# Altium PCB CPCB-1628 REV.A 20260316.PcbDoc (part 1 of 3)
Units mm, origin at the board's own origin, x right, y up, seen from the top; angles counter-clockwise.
Board outline 103 x 58.8 mm, 4 copper layers (Top Layer 1, Layer1, Layer2, Bottom Layer 1), stack 0.603 mm thick; 176 components, 137 nets, 518 pads, 340 vias.
Unrouted connection lines stored in the file: 10.
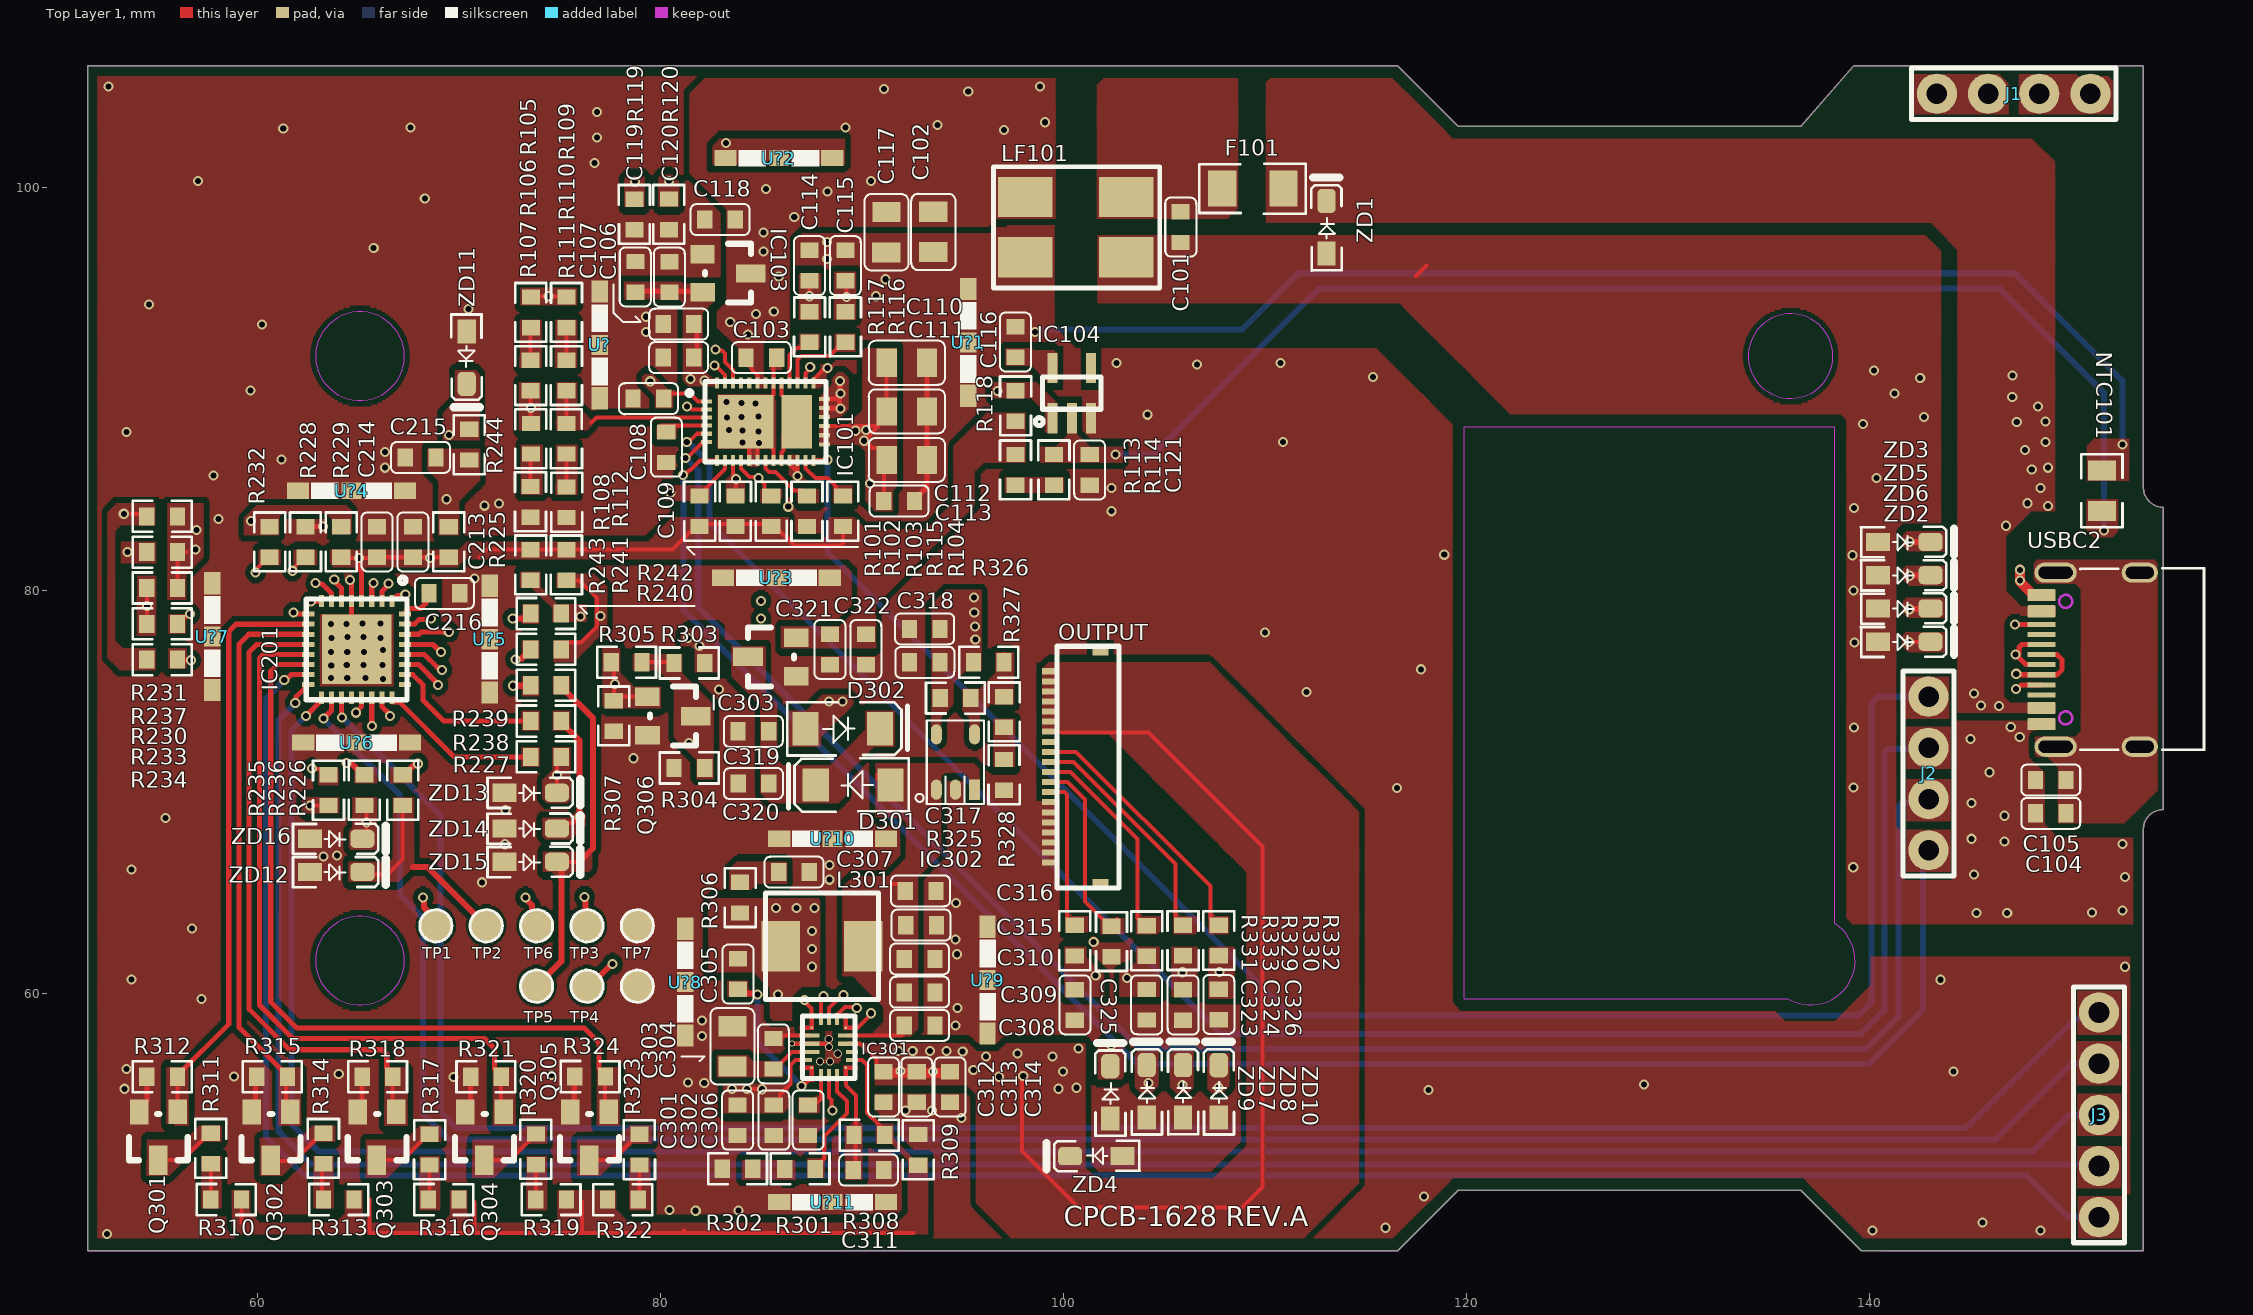
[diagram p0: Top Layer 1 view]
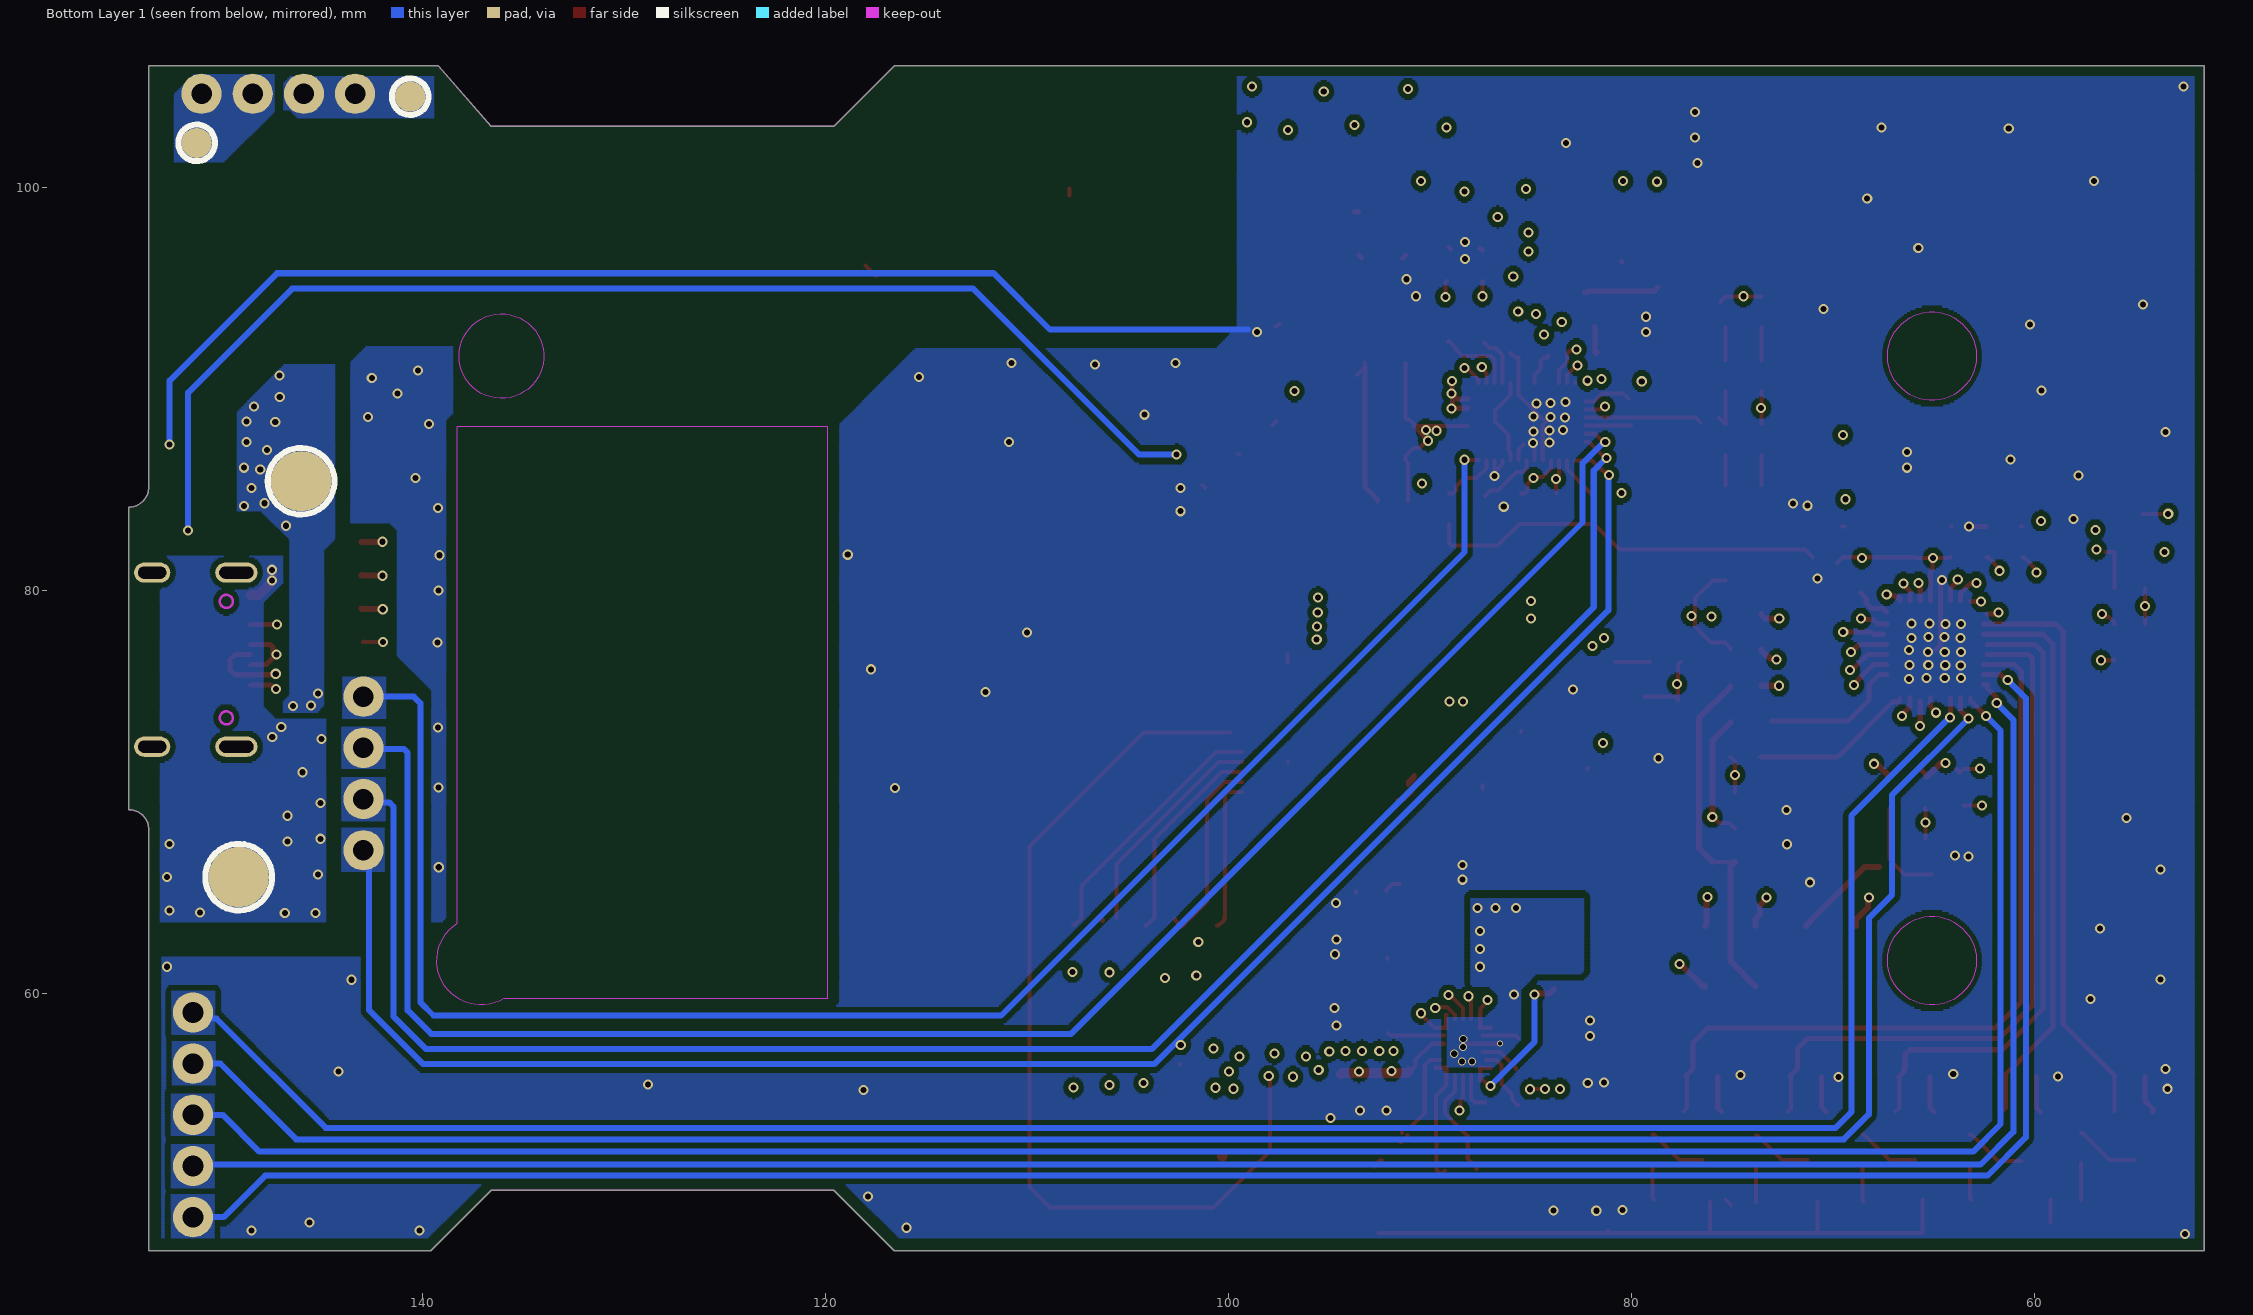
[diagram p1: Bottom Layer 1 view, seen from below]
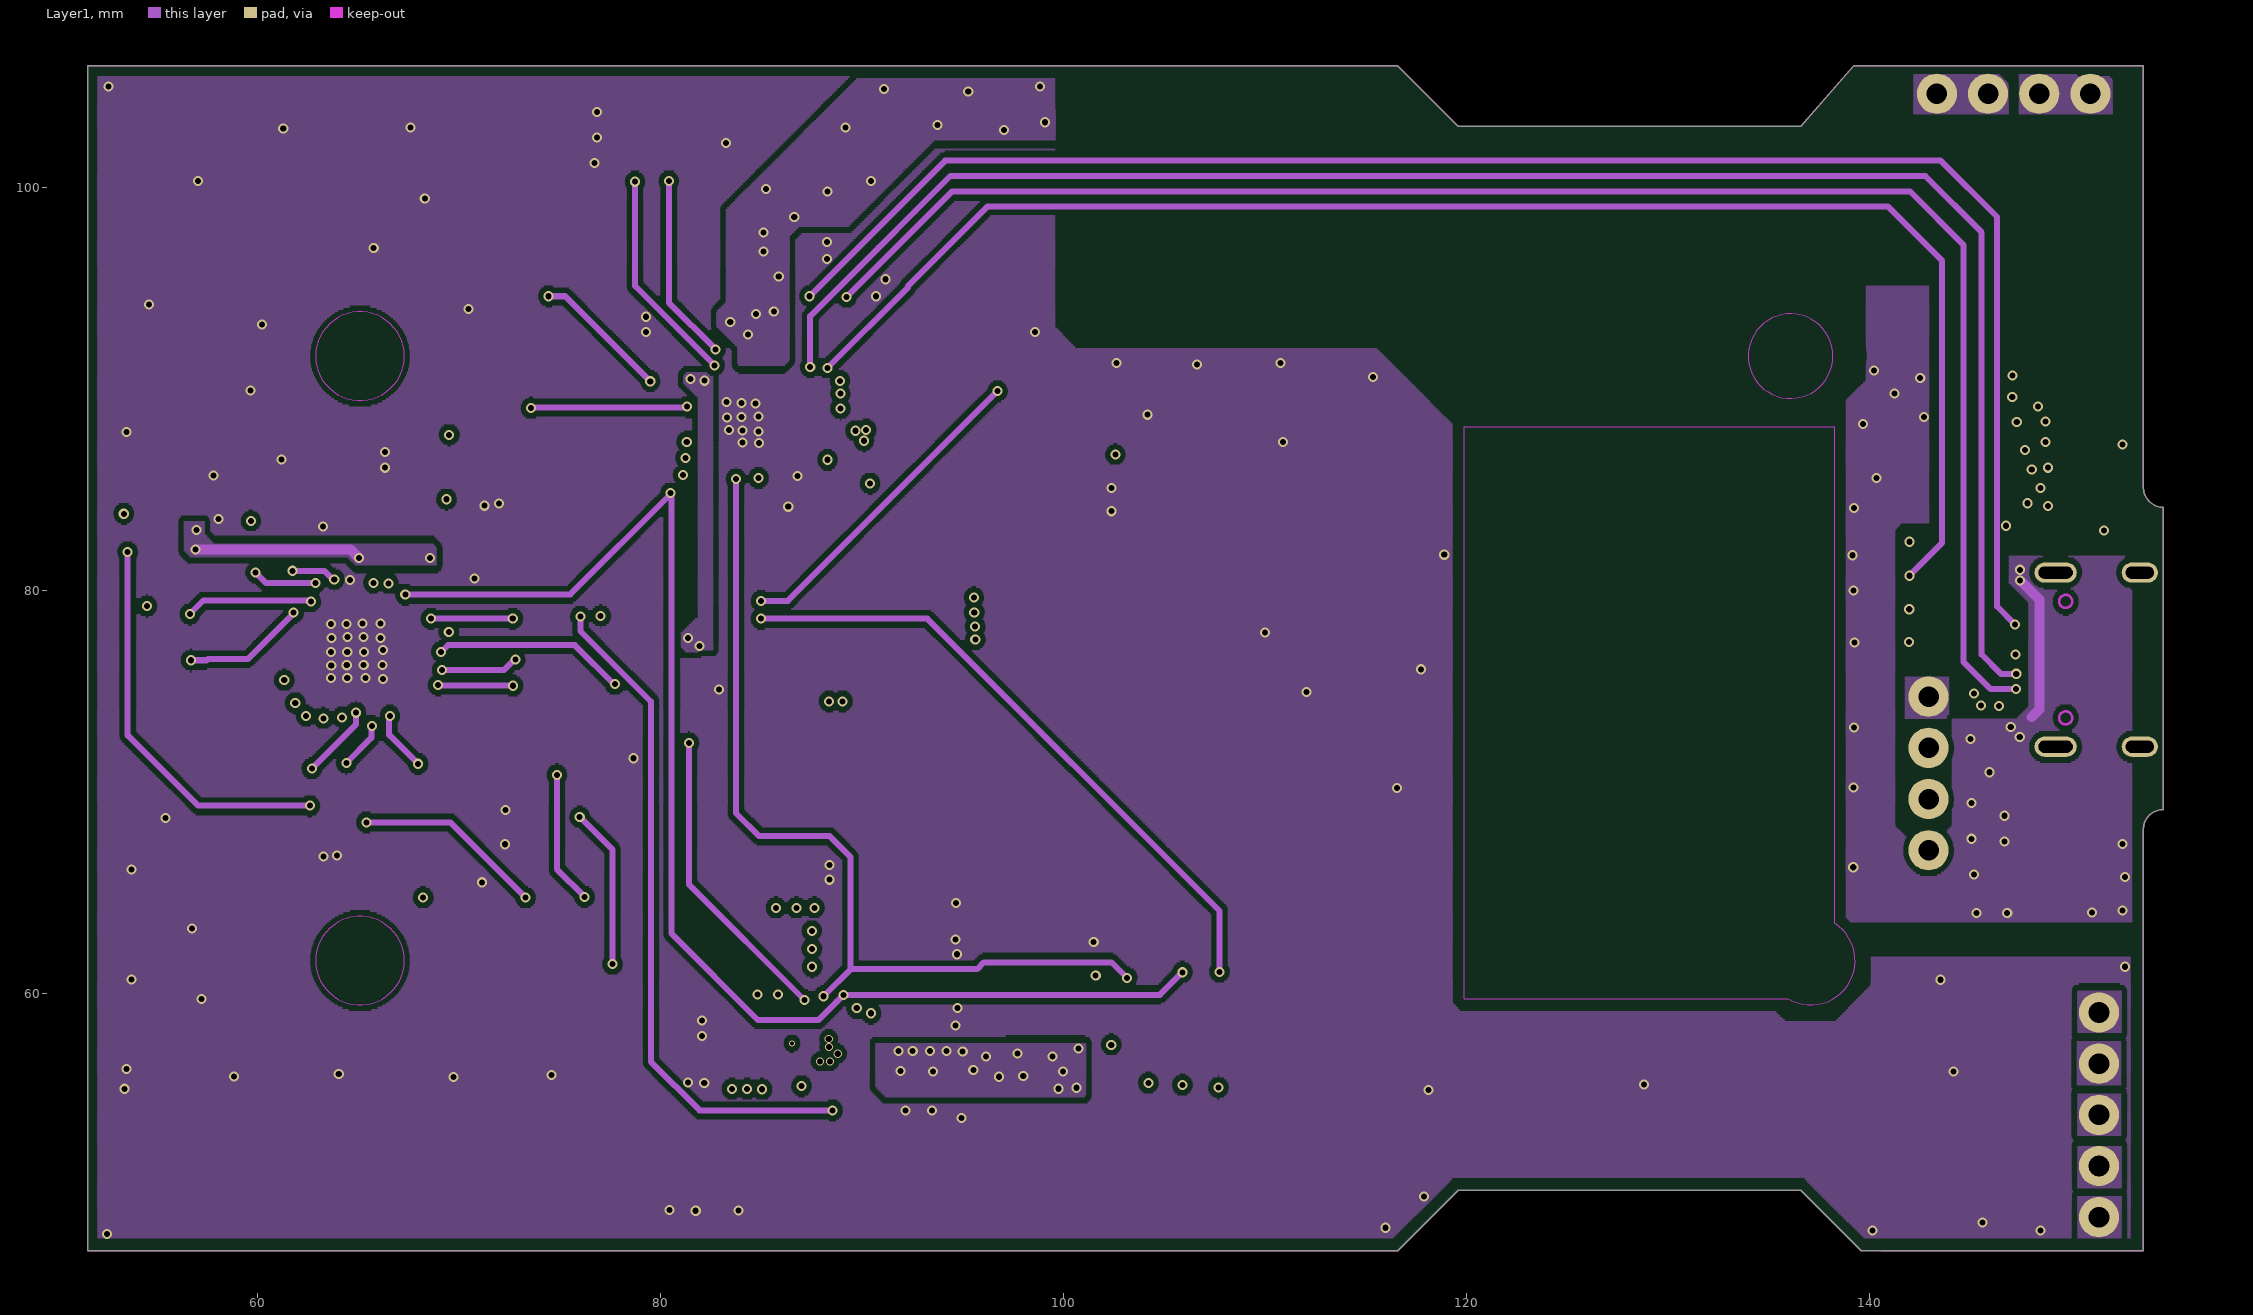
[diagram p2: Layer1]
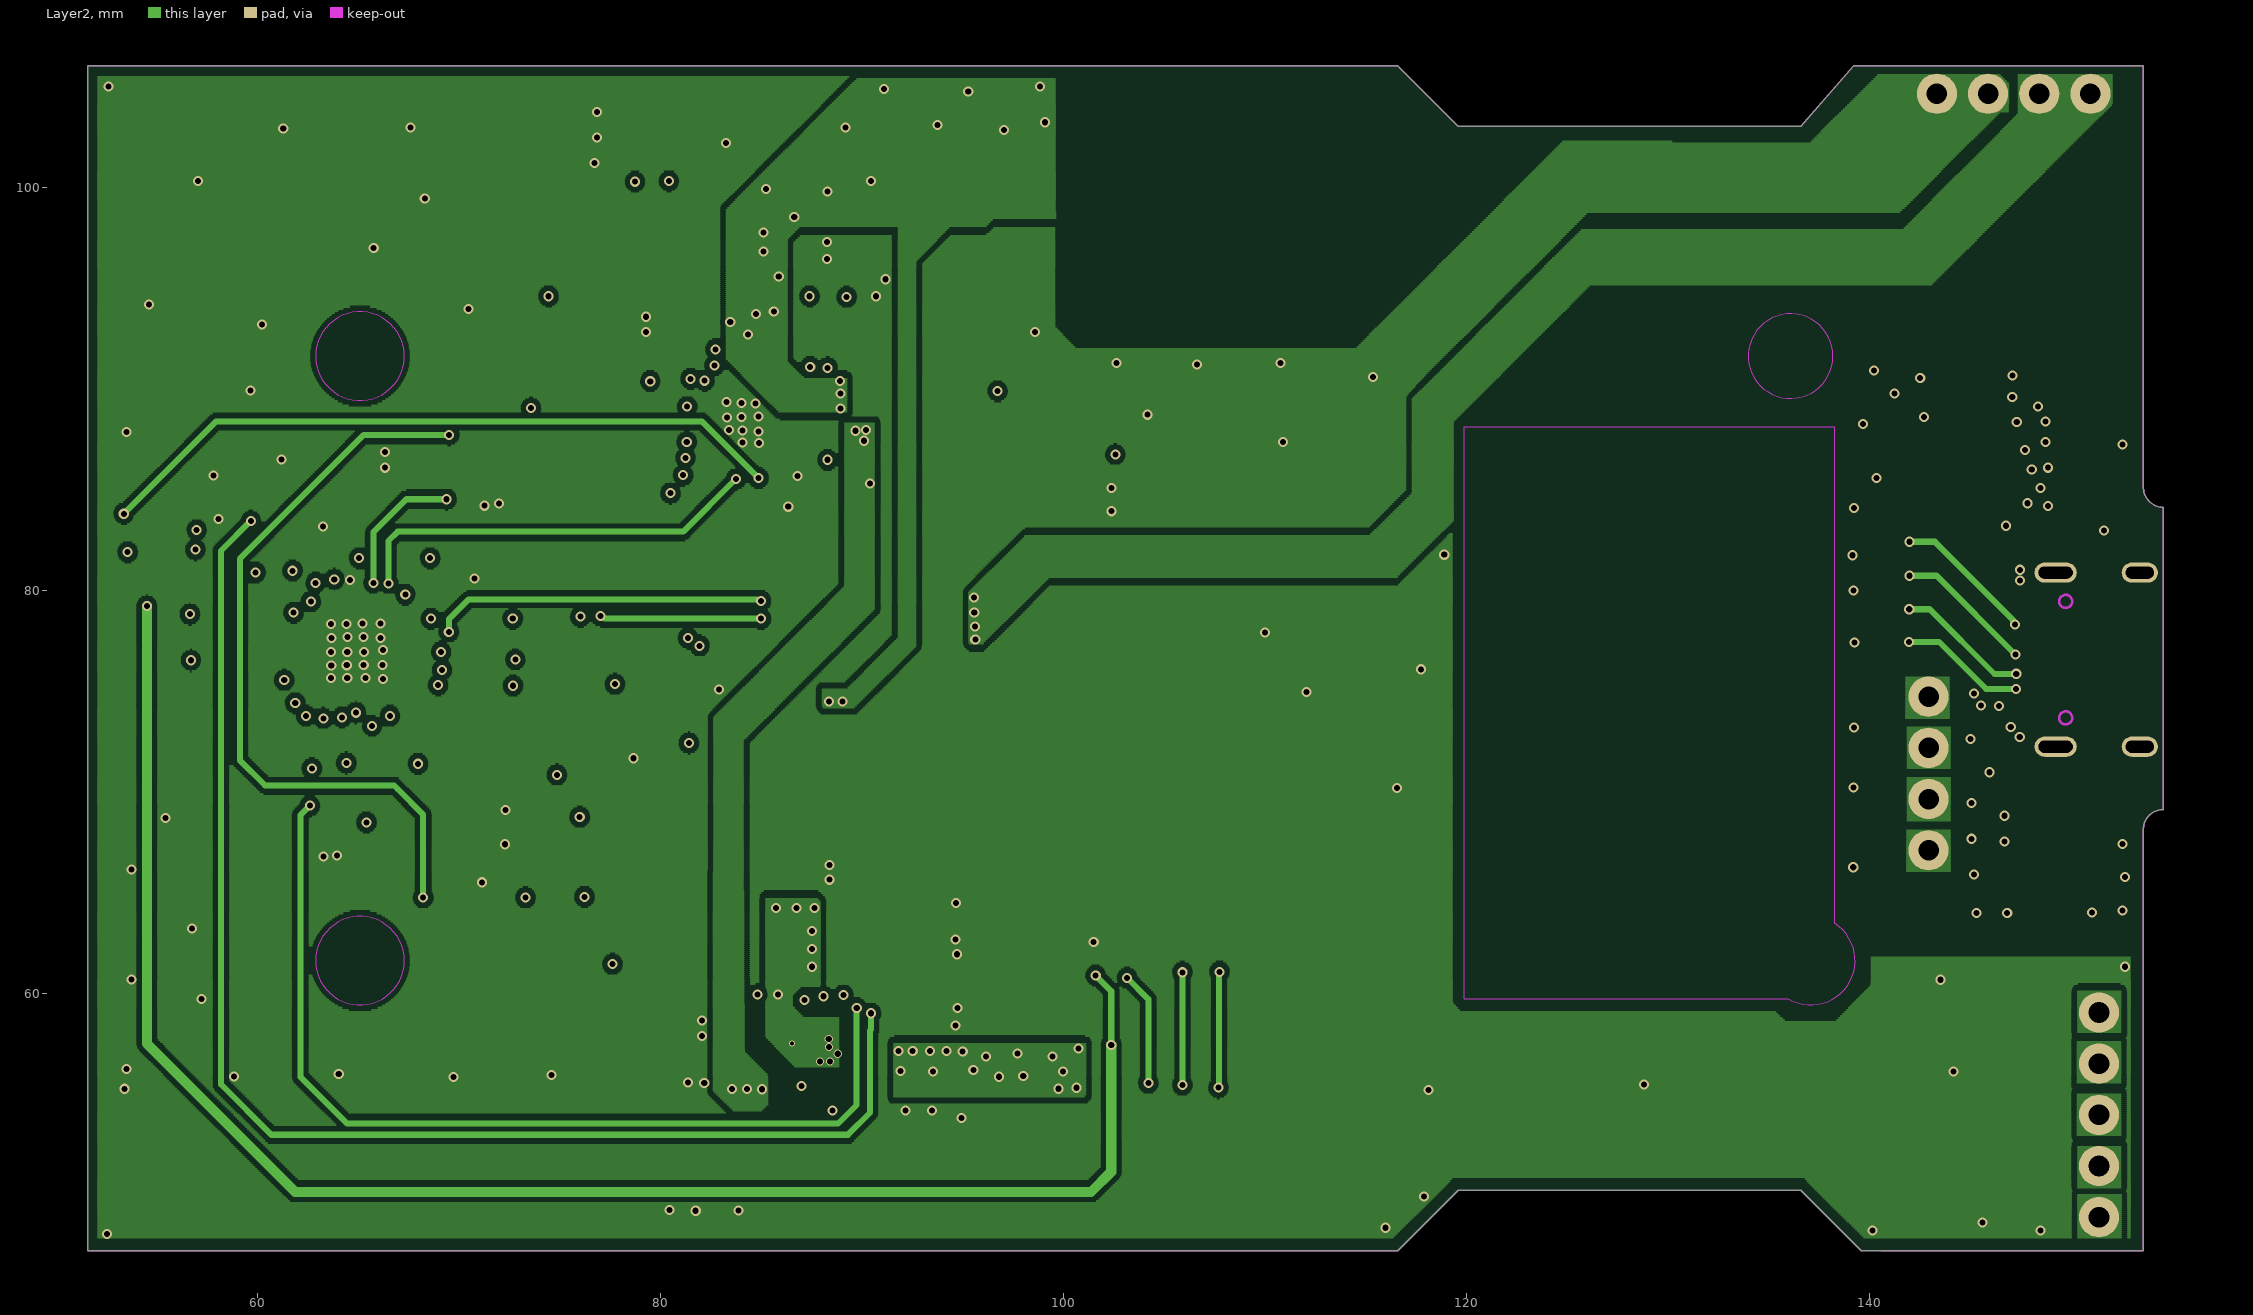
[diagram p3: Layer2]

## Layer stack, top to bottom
Top Solder: solder mask 0.0102, Solder Resist, Dk 3.5
Top Layer 1: signal copper 0.035
Dielectric 1: core 0.0711, PP-006, Dk 4.1
Layer1: signal copper 0.0356
Dielectric 2: dielectric 0.32, FR-4, Dk 4.8
Layer2: signal copper 0.0356
Dielectric 3: core 0.0711, PP-006, Dk 4.1
Bottom Layer 1: signal copper 0.035
Bottom Solder: solder mask 0.0102, Solder Resist, Dk 3.5

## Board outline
51.563,47.243 116.563,47.243 119.563,50.243 136.563,50.243 139.563,47.243 153.563,47.243 153.563,68.143 cw(c154.563,68.143) 154.563,69.143 154.563,84.143 cw(c154.563,85.143) 153.563,85.143 153.563,106.043 139.188,106.043 136.563,103.043 119.563,103.043 116.563,106.043 51.563,106.043

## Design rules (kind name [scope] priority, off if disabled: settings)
Clearance [All] p1: gap=0.254 ignorepadtopadclearanceinfootprint=FALSE except(0: Arc-Hole Track-Hole SMDPad-Hole THPad-Hole Via-Hole Fill-Hole Poly-Hole Region-Hole Text-Hole)
PlaneConnect [All] p1: planeconnectstyle=Direct reliefexpansion=0.508 reliefentries=4 reliefconductorwidth=0.254 reliefairgap=0.254
PolygonConnect [All] p1: connectstyle=Direct reliefconductorwidth=0.254 reliefentries=4 polygonreliefangle="90 Angle" airgapwidth=0.254
RoutingVias [All] p1: holewidth=0.711 width=1.27 viastyle="Through Hole" minholewidth=0.711 minwidth=1.27 maxholewidth=0.711 maxwidth=1.27
SolderMaskExpansion [All] p1: expansion=0.102 istentingtop=FALSE
Width [All] p1: maxlimit=0.5 minlimit=0.2 preferedwidth=0.2
29 further rules are at their usual default settings.

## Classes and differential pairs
component class "CHR-0807.REV.0  20260309": C101 C102 C103 C106 C107 C108 C109 C110 C111 C112 C113 C114 C115 C116 C117 C118 C119 C120 C213 C214 C215 C216 C301 C302 C303 C304 C305 C306 C307 C308 C309 C310 C311 C312 C313 C314 C315 C316 C317 C318 C319 C320 C321 C322 C323 C324 C326 D301 D302 F101 IC101 IC201 IC301 IC302 IC303 LF101 NTC101 P1 P2 Q301 Q302 Q303 Q304 Q305 Q306 R101 R102 R103 R104 R105 R106 R107 R108 R109 R110 R111 R112 R113 R114 R115 R116 R117 R118 R225 R226 R227 R228 R230 R231 R232 R233 R234 R235 R236 R237 R238 R239 R240 R241 R242 R243 R244 R301 R302 R303 R304 R305 R306 R307 R308 R309 R310 R311 R312 R313 R314 R315 R316 R317 R318 R320 R321 R322 R323 R324 R325 R326 R327 R328 R329 R330 R331 R332 R333 ZD1 ZD2 ZD3 ZD4 ZD5 ZD6 ZD7 ZD8 ZD9 ZD10 ZD11 ZD12 ZD13 ZD14 ZD15 ZD16

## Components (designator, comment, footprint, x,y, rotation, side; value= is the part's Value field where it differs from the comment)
C101 "0.1uF/50V" 0603-T-C 105.791,98.044 r270 top
C102 "10uF/25V" 0805-T-C 93.515,97.808 r270 top
C103 "0.1uF/50V" 0603-T-C 84.983,91.567 r0 top
C104 "0.1uF/50V" 0603-T-C 148.971,68.961 r180 top
C105 "0.1uF/50V" 0603-T-C 148.971,70.612 r180 top
C106 "10uF/10V" 0603-T-C 80.874,91.576 r180 top
C107 "0.1uF/50V" 0603-T-C 80.874,93.233 r180 top
C108 "10uF/10V" 0603-T-C 79.375,89.535 r180 top
C109 "10uF/10V" 0603-T-C 80.264,87.122 r270 top
C110 "22uF/25V" 0805-T-C 92.202,91.313 r0 top
C111 "22uF/25V" 0805-T-C 92.202,88.9 r0 top
C112 "22uF/25V" 0805-T-C 92.202,86.487 r0 top
C113 "0.1uF/50V" 0603-T-C 91.823,84.455 r0 top
C114 "330pF/50V" 0603-T-C 87.376,96.139 r90 top
C115 "330pF/50V" 0603-T-C 89.154,96.139 r90 top
C116 "1UF/50V" 0603-T-C 97.596,92.348 r90 top
C117 "10uF/25V" 0805-T-C 91.186,97.79 r270 top
C118 "0.1uF/50V" 0603-T-C 82.931,98.425 r180 top
C119 "10uF/10V" 0603-T-C 78.729,95.58 r90 top
C120 "0.1uF/50V" 0603-T-C 80.419,95.567 r90 top
C121 "1UF/50V" 0603-T-C 101.279,85.998 r90 top (schematic designator C116)
C213 "10uF/10V" 0603-T-C 67.691,82.423 r90 top
C214 "0.1uF/50V" 0603-T-C 65.913,82.423 r90 top
C215 "10nF/50V" 0603-T-C 68.072,86.614 r0 top
C216 "0.47uF/16V" 0603-T-C 69.249,79.877 r180 top
C301 "1uF/25V" 0603-T-C 83.802,53.721 r270 top
C302 "0.1uF/50V" 0603-T-C 85.597,53.723 r270 top
C303 "10uF/25V" 0805-T-C 83.549,57.388 r90 top
C304 "0.1uF/50V" 0603-T-C 85.58,57.023 r90 top
C305 "47nF/50V" 0603-T-C 83.827,60.978 r90 top
C306 "4.7uF/10V" 0603-T-C 87.299,53.721 r270 top
C307 "NC" 0603-T-C 86.598,66.04 r180 top
C308 "22uF/10V" 0603-T-C 92.837,58.42 r0 top
C309 "22uF/10V" 0603-T-C 92.837,60.071 r0 top
C310 "0.1uF/50V" 0603-T-C 92.837,61.722 r0 top
C311 "0.1uF/50V" 0603-T-C 90.303,51.247 r0 top
C312 "10uF/10V" 0603-T-C 91.041,55.372 r270 top
C313 "10uF/10V" 0603-T-C 92.692,55.372 r270 top
C314 "0.1uF/50V" 0603-T-C 94.343,55.372 r270 top
C315 "4.7uF/10V" 0603-T-C 92.912,63.401 r0 top
C316 "0.1uF/50V" 0603-T-C 92.886,65.102 r0 top
C317 "0.1uF/50V" 0603-T-C 93.091,76.454 r180 top
C318 "4.7uF/10V" 0603-T-C 93.091,78.105 r0 top
C319 "10uF/10V" 0603-T-C 84.582,73.025 r180 top
C320 "0.1uF/50V" 0603-T-C 84.59,70.428 r0 top
C321 "0.1uF/50V" 0603-T-C 88.392,77.089 r90 top
C322 "4.7uF/10V" 0603-T-C 90.17,77.089 r90 top
C323 "0.1uF/50V" 0603-T-C 104.106,59.454 r90 top
C324 "0.1uF/50V" 0603-T-C 105.91,59.44 r270 top
C325 "0.1uF/50V" 0603-T-C 100.537,59.444 r270 top
C326 "0.1uF/50V" 0603-T-C 107.681,59.467 r270 top
D301 "SS145" SMAF 89.535,70.358 r0 top
D302 "NU" SMAF 89.027,73.152 r180 top
F101 "F1206HI5000V032TM" 1206-T-R 109.377,99.957 r180 top
IC101 "TPS25751D" QFN-38PIN 85.181,88.392 r0 top
IC103 "CE6022818M" SOT-23 83.312,95.758 r270 top (schematic designator IC303)
IC104 "PST8411" SSOP5 100.39,89.808 r0 top (schematic designator IC102)
IC201 "MSPM0L1105TRHB" QFN-32PIN 64.897,77.089 r270 top
IC301 "BQ25622" QFN-(3_2.5)-18PIN 88.29,57.403 r90 top
IC302 "CE6300" SOT-23(5PIN) 94.615,71.501 r90 top
IC303 "CE6022818M" SOT-23 85.471,76.708 r90 top
J1 "0603" CK_DIP-(10.16_2.54)-4PIN 147.132,104.665 r0 top (schematic designator R302)
J2 "0603" CK_DIP-(10.16_2.54)-4PIN 142.909,70.932 r270 top (schematic designator R302)
J3 "0603" CK_DIP-(10.16_2.54)-6PIN 151.367,59.07 r270 top (schematic designator R302)
L301 "1uH 7A SMP0530" LF-SMD-(5.6_5.3) 87.993,62.357 r0 top
LF101 "LF-ACT45B" CMF7060 100.584,98.044 r270 top
NTC101 "471K" 0805-T-R 151.511,84.963 r270 top
OUTPUT "1k/0603" DZ-(12_3)-20PIN 100.552,71.247 r90 top (schematic designator R304)
Q301 "CJ3400" SOT-23 55.056,52.897 r180 top
Q302 "CJ3400" SOT-23 60.643,52.897 r180 top
Q303 "CJ3400" SOT-23 65.914,52.897 r180 top
Q304 "CJ3400" SOT-23 71.247,52.897 r180 top
Q305 "CJ3400" SOT-23 76.454,52.897 r180 top
Q306 "CJ3400" SOT-23 80.58,73.788 r270 top
R101 "3.3K/0603" 0603-T-R 81.915,83.947 r270 top
R102 "3.3K/0603" 0603-T-R 83.693,83.947 r270 top
R103 "10K/0603" 0603-T-R 85.471,83.947 r270 top
R104 "10K/0603" 0603-T-R 89.027,83.947 r270 top
R105 "2K/0603" 0603-T-R 73.543,93.816 r90 top
R106 "100K/0603" 0603-T-R 73.533,90.68 r90 top
R107 "2K/0603" 0603-T-R 73.543,87.542 r90 top
R108 "2K/0603" 0603-T-R 73.525,84.414 r90 top
R109 "2K/0603" 0603-T-R 75.312,93.816 r90 top
R110 "100K/0603" 0603-T-R 75.311,90.68 r90 top
R111 "2K/0603" 0603-T-R 75.308,87.542 r90 top
R112 "2K/0603" 0603-T-R 75.318,84.391 r90 top
R113 "10K/0603" 0603-T-R 97.596,85.998 r90 top (schematic designator R118)
R114 "10K/0603" 0603-T-R 99.501,85.998 r270 top (schematic designator R118)
R115 "0R/0603" 0603-T-R 87.249,83.947 r90 top
R116 "10R/0603" 0603-T-R 89.154,93.091 r270 top
R117 "10R/0603" 0603-T-R 87.376,93.091 r90 top
R118 "10K/0603" 0603-T-R 97.596,89.173 r270 top
R119 "10R/0603" 0603-T-R 78.682,98.677 r270 top (schematic designator R117)
R120 "10R/0603" 0603-T-R 80.391,98.679 r270 top (schematic designator R117)
R225 "47K/0603" 0603-T-R 69.469,82.423 r270 top
R226 "100R/0603" 0603-T-R 67.183,70.104 r90 top
R227 "100R/0603" 0603-T-R 74.295,71.755 r0 top
R228 "100K/0603" 0603-T-R 62.357,82.423 r90 top
R229 "10K/0603" 0603-T-R 64.135,82.423 r270 top
R230 "10K/0603" 0603-T-R 55.245,80.137 r180 top
R231 "10K/0603" 0603-T-R 55.245,83.693 r0 top
R232 "100R/0603" 0603-T-R 60.579,82.423 r90 top
R233 "100R/0603" 0603-T-R 55.245,78.359 r180 top
R234 "100R/0603" 0603-T-R 55.245,76.581 r180 top
R235 "100R/0603" 0603-T-R 63.5,70.104 r270 top
R236 "100R/0603" 0603-T-R 65.278,70.104 r90 top
R237 "10K/0603" 0603-T-R 55.245,81.915 r0 top
R238 "100R/0603" 0603-T-R 74.295,73.533 r0 top
R239 "100R/0603" 0603-T-R 74.295,75.311 r0 top
R240 "100R/0603" 0603-T-R 74.295,77.089 r0 top
R241 "10K/0603" 0603-T-R 75.311,81.282 r90 top
R242 "100R/0603" 0603-T-R 74.295,78.867 r0 top
R243 "10K/0603" 0603-T-R 73.533,81.282 r90 top
R244 "100R/0603" 0603-T-R 70.485,87.249 r90 top
R301 "0603" 0603-T-R 86.904,51.308 r0 top
R302 "0603" 0603-T-R 83.799,51.313 r0 top
R303 "10K/0603" 0603-T-R 81.405,76.413 r0 top
R304 "1k/0603" 0603-T-R 81.405,71.206 r180 top
R305 "100R/0603" 0603-T-R 78.296,76.455 r180 top
R306 "NC" 0603-T-R 83.929,64.77 r270 top
R307 "100k/0603" 0603-T-R 77.659,73.788 r270 top
R308 "0603" 0603-T-R 90.34,52.986 r180 top
R309 "0603" 0603-T-R 92.77,52.255 r270 top
R310 "0603" 0603-T-R 58.42,49.784 r0 top
R311 "0603" 0603-T-R 57.658,52.324 r270 top
R312 "10K/0603" 0603-T-R 55.247,55.88 r0 top
R313 "0603" 0603-T-R 64.008,49.784 r0 top
R314 "0603" 0603-T-R 63.246,52.324 r270 top
R315 "10K/0603" 0603-T-R 60.706,55.88 r0 top
R316 "0603" 0603-T-R 69.215,49.784 r0 top
R317 "0603" 0603-T-R 68.518,52.262 r90 top
R318 "10K/0603" 0603-T-R 65.933,55.883 r0 top
R319 "0603" 0603-T-R 74.549,49.784 r0 top
R320 "0603" 0603-T-R 73.79,52.281 r90 top
R321 "10K/0603" 0603-T-R 71.312,55.88 r0 top
R322 "0603" 0603-T-R 78.105,49.784 r180 top
R323 "0603" 0603-T-R 78.932,52.262 r90 top
R324 "10K/0603" 0603-T-R 76.483,55.887 r0 top
R325 "12K/0603" 0603-T-R 94.615,74.676 r180 top
R326 "12K/0603" 0603-T-R 96.266,76.454 r180 top
R327 "1K/0603" 0603-T-R 97.03,73.985 r90 top
R328 "1K/0603" 0603-T-R 97.028,70.866 r90 top
R329 "100R/0603" 0603-T-R 104.106,62.622 r90 top
R330 "100R/0603" 0603-T-R 105.91,62.64 r90 top
R331 "100R/0603" 0603-T-R 100.537,62.632 r90 top
R332 "100R/0603" 0603-T-R 107.681,62.642 r90 top
R333 "100R/0603" 0603-T-R 102.359,62.59 r90 top
U? "Comment" SMD_3P-L6.7-W0.9-R3-P2.65-ICSRC6508SFR 76.962,92.202 r90 top
U?1 "Comment" SMD_3P-L6.7-W0.9-R3-P2.65-ICSRC6508SFR 95.25,92.329 r90 top
U?2 "Comment" SMD_3P-L6.7-W0.9-R3-P2.65-ICSRC6508SFR 85.852,101.473 r180 top
U?3 "Comment" SMD_3P-L6.7-W0.9-R3-P2.65-ICSRC6508SFR 85.725,80.645 r180 top
U?4 "Comment" SMD_3P-L6.7-W0.9-R3-P2.65-ICSRC6508SFR 64.643,84.963 r180 top
U?5 "Comment" SMD_3P-L6.7-W0.9-R3-P2.65-ICSRC6508SFR 71.501,77.597 r270 top
U?6 "Comment" SMD_3P-L6.7-W0.9-R3-P2.65-ICSRC6508SFR 64.897,72.463 r0 top
U?7 "Comment" SMD_3P-L6.7-W0.9-R3-P2.65-ICSRC6508SFR 57.731,77.724 r90 top
U?8 "Comment" SMD_3P-L6.7-W0.9-R3-P2.65-ICSRC6508SFR 81.207,60.579 r90 top
U?9 "Comment" SMD_3P-L6.7-W0.9-R3-P2.65-ICSRC6508SFR 96.209,60.674 r90 top
U?10 "Comment" SMD_3P-L6.7-W0.9-R3-P2.65-ICSRC6508SFR 88.519,67.691 r180 top
U?11 "Comment" SMD_3P-L6.7-W0.9-R3-P2.65-ICSRC6508SFR 88.519,49.657 r0 top
USBC2 "TYPE-C16PIN" TYPE-C-16pin 151.003,76.581 r0 top (schematic designator USBC1)
ZD1 "ESD24C" SOD-323-B 113.03,98.044 r270 top
ZD2 "ESD24C" SOD-323-B 141.705,77.47 r180 top
ZD3 "ESD24C" SOD-323-B 141.705,82.423 r180 top
ZD4 "ESD05C" SOD-323-B 101.6,51.943 r0 top
ZD5 "ESD05C" SOD-323-B 141.705,80.772 r180 top
ZD6 "ESD05C" SOD-323-B 141.705,79.121 r180 top
ZD7 "ESD05C" SOD-323-B 104.106,55.156 r270 top
ZD8 "ESD05C" SOD-323-B 105.91,55.163 r270 top
ZD9 "ESD05C" SOD-323-B 102.297,55.103 r270 top
ZD10 "ESD05C" SOD-323-B 107.681,55.156 r270 top
ZD11 "ESD05C" SOD-323-B 70.358,91.567 r90 top
ZD12 "ESD05C" SOD-323-B 63.881,66.04 r180 top
ZD13 "ESD05C" SOD-323-B 73.533,69.977 r180 top
ZD14 "ESD05C" SOD-323-B 73.533,68.199 r180 top
ZD15 "ESD05C" SOD-323-B 73.533,66.548 r180 top
ZD16 "ESD05C" SOD-323-B 63.881,67.691 r180 top

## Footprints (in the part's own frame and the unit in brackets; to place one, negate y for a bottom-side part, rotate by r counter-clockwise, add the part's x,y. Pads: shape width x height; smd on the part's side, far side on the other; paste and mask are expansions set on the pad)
0603-T-C [mm]
  rect 0.76x0.9 smd mask+0.05: 1(-0.76,0) 2(0.76,0)
  silkscreen extent -1.47,-0.76 1.46,0.78
0603-T-R [mm]
  rect 0.76x0.9 smd mask+0.05: 1(-0.76,0) 2(0.76,0)
  silkscreen extent -1.46,-0.77 1.46,0.77
0805-T-C [mm]
  rect 1x1.4 smd mask+0.05: 1(-1,0.001) 2(1,-0.001)
  silkscreen extent -1.9,-1.1 1.9,1.1
0805-T-R [mm]
  rect 1x1.4 smd mask+0.05: 1(-1,0.001) 2(1,-0.001)
  silkscreen extent -1.82,-1.02 1.82,1.02
1206-T-R [mm]
  rect 1.4x1.78 smd: 1(-1.52,0) 2(1.52,0)
  silkscreen extent -2.63,-1.24 2.66,1.24
CK_DIP-(10.16_2.54)-4PIN [mm]
  round 2 hole 1.02 mask+0.05: 1(-3.81,0) 2(-1.27,0)
  round 2 hole 1.02: 3(1.27,0) 4(3.81,0)
  silkscreen extent -5.08,-1.27 5.08,1.27
CK_DIP-(10.16_2.54)-6PIN [mm]
  round 2 hole 1.02: 1(0,0) 2(2.54,0) 3(5.08,0) 4(7.62,0) 5(10.16,0)
  silkscreen extent -1.27,-1.27 11.43,1.27
CMF7060 [mm]
  rect 2x2.7 smd: 1(-1.5,2.5) 2(1.5,2.5) 3(1.5,-2.5) 4(-1.5,-2.5)
  silkscreen extent -2.99,-4.08 3.01,4.17
DZ-(12_3)-20PIN [mm]
  rect 0.4x0.8 smd: 0(-5.75,-1.252) 0(5.75,-1.252)
  rect 0.3x0.8 smd: 1(-4.742,1.252) 2(-4.242,1.252) 3(-3.742,1.252) 4(-3.242,1.252) 5(-2.742,1.252) 6(-2.242,1.252) 7(-1.742,1.252) 8(-1.242,1.252) 9(-0.742,1.252) 10(-0.242,1.252) 11(0.258,1.252) 12(0.758,1.252) 13(1.258,1.252) 14(1.758,1.252) 15(2.258,1.252) 16(2.758,1.252) 17(3.258,1.252) 18(3.758,1.252) 19(4.258,1.252) 20(4.758,1.252)
  silkscreen extent -6,-2.19 6,0.91
LF-SMD-(5.6_5.3) [mm]
  rect 1.9x2.5 smd: 1(-2.05,0) 2(2.05,0)
  silkscreen extent -2.8,-2.65 2.8,2.65
QFN-32PIN [mm]
  rect 3.45x3.45 smd: 0(0,0)
  rect 0.6x0.25 smd: 1(-2.4,1.75) 2(-2.4,1.25) 3(-2.4,0.75) 4(-2.4,0.25) 5(-2.4,-0.25) 6(-2.4,-0.75) 7(-2.4,-1.25) 8(-2.4,-1.75) 17(2.4,-1.75) 18(2.4,-1.25) 19(2.4,-0.75) 20(2.4,-0.25) 21(2.4,0.25) 22(2.4,0.75) 23(2.4,1.25) 24(2.4,1.75)
  rect 0.25x0.6 smd: 9(-1.75,-2.4) 10(-1.25,-2.4) 11(-0.75,-2.4) 12(-0.25,-2.4) 13(0.25,-2.4) 14(0.75,-2.4) 15(1.25,-2.4) 16(1.75,-2.4) 25(1.75,2.4) 26(1.25,2.4) 27(0.75,2.4) 28(0.25,2.4) 29(-0.25,2.4) 30(-0.75,2.4) 31(-1.25,2.4) 32(-1.75,2.4)
  silkscreen extent -3.59,-2.5 2.5,2.5
QFN-38PIN [mm]
  rect 2.75x2.65 smd: 0(-0.965,0)
  rect 1.53x2.65 smd: 0(1.56,0)
  rect 0.55x0.2 smd: 1(-2.925,1) 2(-2.925,0.6) 3(-2.925,0.2) 4(-2.925,-0.2) 5(-2.925,-0.6) 6(-2.925,-1) 20(2.925,-1.125) 21(2.925,-0.675) 22(2.925,-0.225) 23(2.925,0.225) 24(2.925,0.675) 25(2.925,1.125)
  rect 0.2x0.55 smd: 7(-2.4,-1.925) 8(-2,-1.925) 9(-1.6,-1.925) 10(-1.2,-1.925) 11(-0.8,-1.925) 12(-0.4,-1.925) 13(0,-1.925) 14(0.4,-1.925) 15(0.8,-1.925) 16(1.2,-1.925) 17(1.6,-1.925) 18(2,-1.925) 19(2.4,-1.925) 26(2.4,1.925) 27(2,1.925) 28(1.6,1.925) 29(1.2,1.925) 30(0.8,1.925) 31(0.4,1.925) 32(0,1.925) 33(-0.4,1.925) 34(-0.8,1.925) 35(-1.2,1.925) 36(-1.6,1.925) 37(-2,1.925) 38(-2.4,1.925)
  silkscreen extent -3.89,-2 3,2
QFN-(3_2.5)-18PIN [mm]
  rect 0.127x0.127 smd paste-0.064 mask-0.064: 1(-1.085,0.813) 5(-1.085,-0.887) 10(0.915,-0.887) 14(0.915,0.813)
  rect 0.625x0.2 smd: 2(-1.448,0.356) 3(-1.448,-0.044) 4(-1.448,-0.444)
  rect 0.2x0.6 smd: 6(-0.685,-1.187) 7(-0.285,-1.187)
  rect 0.2x1 smd: 8(0.115,-0.987) 9(0.515,-0.987) 15(0.515,0.913) 17(-0.285,0.913)
  rect 0.6x0.2 smd: 11(1.34,-0.444) 12(1.34,-0.044) 13(1.34,0.356)
  rect 0.2x1 smd paste-0.5: 16(0.115,0.913)
  rect 0.2x0.619 smd: 18(-0.685,1.104)
  Top Layer 1 region: -1.185,0.913 -1.761,0.913 -1.761,0.713 -0.985,0.713 -0.985,1.413 -1.185,1.413
  Top Layer 1 region: -1.185,-0.987 -1.761,-0.987 -1.761,-0.787 -0.985,-0.787 -0.985,-1.487 -1.185,-1.487
  Top Layer 1 region: 1.015,-1.487 0.815,-1.487 0.815,-0.787 1.64,-0.787 1.64,-0.987 1.015,-0.987
  Top Layer 1 region: 1.015,1.413 0.815,1.413 0.815,0.713 1.64,0.713 1.64,0.913 1.015,0.913
  silkscreen extent -1.61,-1.33 1.49,1.26
SMAF [mm]
  rect 1.3x1.65 smd: 1(1.85,0) 2(-1.85,0)
  silkscreen extent -3.21,-1.32 2.77,1.33
SMD_3P-L6.7-W0.9-R3-P2.65-ICSRC6508SFR [mm]
  rect 1.1x0.8 smd paste+0 mask+0.05: 1(-2.65,0) 3(2.65,0)
  rect 1x0.8 smd paste+0 mask+0.05: 2(0,0)
  silkscreen extent -2,-0.4 2,0.4
SOD-323-B [mm]
  rect 1.2x0.9 smd: 1(1.3,0)
  rrect50% 1.2x0.9 smd: 2(-1.3,0)
  silkscreen extent -2.46,-0.75 2.16,0.76
SOT-23 [mil]
  rect 36x47.8 smd: 1(-37.5,-49.25)
  rect 36x48.58 smd: 2(37.5,-48.86)
  rect 36x57.87 smd: 3(0.5,45.31)
  silkscreen extent -57,-44 58,46
SOT-23(5PIN) [mm]
  oval 1x0.55 smd: 1(-1.375,0.95) 2(-1.375,0) 4(1.375,-0.95) 5(1.375,0.95)
  rect 1x0.55 smd: 3(-1.375,-0.95)
  silkscreen extent -2.09,-1.42 2.07,1.98
SSOP5 [mm]
  rect 0.5x1.5 smd: 1(-0.95,-1.25) 2(0,-1.25) 3(0.95,-1.25) 4(0.95,1.25) 5(-0.95,1.25)
  silkscreen extent -1.81,-1.61 1.45,0.8
TYPE-C-16pin [mm]
  oval 2.1x1 hole 0.6 slot 1.7 at 0 deg: 1(-1.79,4.32) 4(-1.79,-4.32)
  oval 1.8x1 hole 0.6 slot 1.4 at 0 deg: 2(2.39,4.32) 3(2.39,-4.32)
  rrect20% 1.4x0.6 smd: A1B12(-2.49,-3.2) A4B9(-2.49,-2.4) A12B1(-2.49,3.2) B4A9(-2.49,2.4)
  rrect20% 1.4x0.25 smd: A5(-2.49,-1.25) A6(-2.49,-0.25) "A7 D-"(-2.49,0.25) "A8 SBU1"(-2.49,1.25) B5(-2.49,1.75) B6(-2.49,0.75) B7(-2.49,-0.75) "B8 SBU2"(-2.49,-1.75)
  silkscreen extent -0.57,-4.47 5.58,4.53

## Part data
C101 C102 C103 C104 C105 C106 C107 C108 C109 C110 C111 C112 C113 C114 C115 C116 C117 C118 C119 C120 C121 C213 C214 C215 C216 C301 C302 C303 C304 C305 C306 C307 C308 C309 C310 C311 C312 C313 C314 C315 C316 C317 C318 C319 C320 C321 C322 C323 C324 C325 C326: library part "SMD C0603", "Capacitor SMD 0603"
D301 D302: library part Diode, "Default Diode", PackageDocument=Sep-1996
F101: library part "Fuse Thermal", "Thermal Fuse"
IC103 IC302 IC303: library part TLV75533, "7P接插件"
J1 J2 J3 OUTPUT R101 R102 R103 R104 R105 R106 R107 R108 R109 R110 R111 R112 R113 R114 R115 R116 R117 R118 R119 R120 R225 R226 R227 R228 R229 R230 R231 R232 R233 R234 R235 R236 R237 R238 R239 R240 R241 R242 R243 R244 R301 R302 R303 R304 R305 R306 R307 R308 R309 R310 R311 R312 R313 R314 R315 R316 R317 R318 R319 R320 R321 R322 R323 R324 R325 R326 R327 R328 R329 R330 R331 R332 R333: library part R0603, "Res,", (m)Manufacturer=Standard, (m)Resistance (Ohms)=0Ω/0805
L301: library part L-CDRH, "功率屏蔽电感"
LF101: "共模电感"
NTC101: library part RT, "热敏电阻"
Q301 Q302 Q303 Q304 Q305 Q306: library part MOSFET-N, "N-Channel MOSFET", PackageDocument=1995/1996
USBC2: "USB-Type C_卧式母座_3A_250VAC_16PIN,8.94*7.3mm_-55~85℃_RoHS", BOM_Manufacturer="SHOU HAN"
ZD1 ZD2 ZD3 ZD4 ZD5 ZD6 ZD7 ZD8 ZD9 ZD10 ZD11 ZD12 ZD13 ZD14 ZD15 ZD16: library part "TVS DO-214AC&SMA", "TVS DIODE DO-201AC&SMA_01"

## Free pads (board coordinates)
  round 1.5 smd: 1(68.827,63.373) 1(71.327,63.373) 1(73.827,60.373) 1(73.827,63.373) 1(76.327,60.373) 1(76.327,63.373) 1(78.827,60.373) 1(78.827,63.373)
  round 1.5 smd far side: 1(140.589,104.521) 1(151.185,102.227)
  round 3 smd far side: 1(146.001,85.434) 1(149.098,65.786)

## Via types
v1: diameter 0.5, hole 0.3, Top Layer 1 to Bottom Layer 1, 334 vias
v2: diameter 0.4, hole 0.3, Top Layer 1 to Bottom Layer 1, 5 vias
v3: diameter 0.3, hole 0.2, Top Layer 1 to Bottom Layer 1, 1 vias

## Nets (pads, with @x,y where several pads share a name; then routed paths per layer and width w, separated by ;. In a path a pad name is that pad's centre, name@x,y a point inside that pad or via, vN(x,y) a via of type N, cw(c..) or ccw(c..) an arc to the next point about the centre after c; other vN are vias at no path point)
+1.8V: C213.1 C214.1 C321.2 C322.2 IC201.4 IC303.2 R101.2 R102.2 R103.2 R104.2 R113.2 R118.2 R225.2 R229.2 R230.1 R231.2 R237.2 R241.2 R243.2 | length 38.9
  Top Layer 1 w0.2: R230.1@56.005,80.137 R237.2@56.005,81.915 56.445,81.915 ; R229.2@64.135,81.663 64.181,81.617 v1(65.024,81.617) ; 65.047,81.067 65.047,81.607 65.037,81.617 65.867,81.617 C214.1@65.913,81.663 69.488,81.663 R225.2@69.768,81.383 ; 70.995,81.663 71.374,82.042 R243.2@73.533,82.042 R241.2@75.311,82.042 80.571,82.042 81.845,83.316 81.915,83.316 81.917,83.314 83.693,83.314 85.471,83.314 85.541,83.314 86.614,82.241 88.91,82.241 89.027,82.358 R104.2@89.027,83.314 ; R118.2@97.596,88.413 R118.2@97.784,88.225
  Top Layer 1 w0.254: 65.047,81.067 65.147,80.967 IC201.4@65.147,79.489
  Layer1 w0.5: v1(56.896,82.042) 64.599,82.042 v1(65.024,81.617)
  other v1: 68.547,81.616 56.957,83.021
+3.2V: C317.1 C318.2 IC302.5 J1.3 J1.4 pad.1@151.185,102.227 R325.2 R326.2 | length 0.6
  Bottom Layer 1 w0.3: J1.3@148.14,104.037 J1.3@148.14,104.638
  other v1: 95.598,77.58 95.593,78.221 95.548,78.926 95.53,79.667
+3.3V: C106.1 C107.1 C119.1 C120.1 IC101.38 IC103.2 R303.2 | length 5.3
  Top Layer 1 w0.2: v1(82.169,90.424) v1@82.223,90.37 ; IC101.38@82.781,90.317 IC101.38@82.781,90.37
  Top Layer 1 w0.254: C119.1@78.659,95.076 C119.1@78.794,94.94 ; C119.1@78.805,94.865 80.448,94.865 82.134,94.865 82.191,94.808 IC103.2@82.336,94.808 ; C106.1@81.66,91.848 C106.1@81.765,91.743 ; C106.1@81.787,91.848 81.787,92.455 81.788,92.456 81.787,92.457 81.787,93.089 C107.1@81.816,93.118
  other v1: 81.916,77.264 81.346,77.645 81.469,90.508
+VBUS: C102.1 C103.1 C117.1 C118.1 D302.1 IC101.23 IC101.24 IC101.25 IC101.32 IC101.33 IC103.3 LF101.4 | length 5
  Top Layer 1 w0.2: C103.1@84.328,91.567 84.483,91.412 84.483,91.009 84.6,90.892 84.605,90.892 84.781,90.716 84.781,90.551 IC101.33@84.781,90.317
  Top Layer 1 w0.254: C103.1@84.114,91.656 C103.1@84.203,91.567 ; IC101.24@88.106,89.067 88.113,89.06 v1@88.899,89.06 ; IC101.25@88.106,89.517 88.628,89.517 v1(88.9,89.789) ; v1@88.824,89.713 88.859,89.678 88.859,89.1 v1@88.899,89.06 ; v1@88.859,88.892 88.859,89.006 v1(88.906,89.053) v1@88.899,89.06 ; v1(88.878,90.406) 88.889,90.395 v1@88.889,89.778 ; C102.1@93.517,98.808 C102.1@93.717,98.808
  other v1: 88.346,74.503 89.007,74.514 84.328,92.71 83.439,93.345 84.709,93.726 85.598,93.853 85.846,95.601 85.081,96.842 85.09,97.79 86.614,98.552 88.265,99.822 85.217,99.949 90.424,100.33 97.028,102.87 89.154,102.997 93.726,103.124 99.06,103.251 95.25,104.775 91.059,104.902 98.806,105.029
ADCIN1: IC101.2 R106.1 R107.2 | length 10.5
  Top Layer 1 w0.2: R107.2@73.533,88.267 73.533,89.065 R106.1@73.533,89.92 ; v1(81.301,89.142) 81.382,89.142 81.532,88.992 IC101.2@82.256,88.992
  Layer1 w0.2: v1(73.545,89.065) v1@73.584,89.103 ; v1@81.263,89.103 v1(81.301,89.142)
  Layer1 w0.3: v1@73.584,89.103 v1@81.263,89.103
ADCIN2: IC101.3 R110.1 R111.2 | length 7.9
  Top Layer 1 w0.2: R110.1@75.311,89.92 75.311,88.265 R111.2@75.628,88.582 ; 76.561,88.341 76.812,88.592 IC101.3@82.256,88.592
ATTACH: C326.1 R240.2 R241.1 R332.1 ZD10.2 | length 51.1
  Top Layer 1 w0.2: R240.2@75.055,77.089 75.055,77.159 75.335,77.439 76.036,77.439 76.835,78.238 76.835,79.629 75.944,80.52 75.313,80.52 R241.1@75.311,80.522
  Layer1 w0.3: v1(84.963,78.613) 93.218,78.613 107.719,64.112 v1(107.719,61.085)
  Layer2 w0.3: v1(77.009,78.755) 77.063,78.755 77.205,78.613 v1(84.963,78.613) ; v1(107.669,55.347) 107.694,55.372 107.694,61.06 v1(107.719,61.085)
BAT+: C312.1 C313.1 C314.1 IC301.8 OUTPUT.14 OUTPUT.15 OUTPUT.16 OUTPUT.17 OUTPUT.18 OUTPUT.19 OUTPUT.20 ZD4.2 | length 52.6
  Top Layer 1 w0.2: IC301.8@89.277,57.518 89.901,57.518 90.691,56.728 90.691,56.412 90.971,56.132 C312.1@91.041,56.132 ; v1@97.917,56.1 97.917,52.197 98.22,51.894 100.711,49.403 108.839,49.403 109.855,50.419 109.855,67.31 104.199,72.966 99.89,72.966
  Top Layer 1 w0.5: C312.1@91.041,56.132 91.11,56.063 94.343,56.063 C314.1@94.399,56.007 ; ZD4.2@100.287,51.93 ZD4.2@100.3,51.943
  other v1: 99.732,55.285 100.628,55.335 96.774,55.88 97.98,55.921 99.949,56.134 91.89,56.16 93.495,56.149 95.5,56.217 96.139,56.896 99.441,56.896 97.689,57.032 94.975,57.134 91.779,57.153 92.494,57.153 93.345,57.15 94.178,57.153 100.711,57.277
BQ25622_CE_N: IC201.29 Q306.1 R305.2 R307.1 | length 15.2
  Top Layer 1 w0.2: v1@69.064,76.962 v1(69.088,76.962) ; R305.2@77.536,76.455 77.659,76.332 77.659,75.365 R307.1@77.659,74.548 77.851,74.741 Q306.1@79.329,74.741
  Top Layer 1 w0.254: IC201.29@67.297,77.339 68.687,77.339 v1@69.064,76.962
  Layer1 w0.3: v1(69.088,76.962) 69.431,77.305 75.73,77.305 v1@77.717,75.318
  other v1: 77.715,75.365
"BSL UART_RX": pad.1@76.327,60.373 R238.2 ZD14.2 | length 16.3
  Top Layer 1 w0.2: ZD14.2@74.833,68.199 75.106,68.472 75.63,68.472 75.933,68.775 v1(75.968,68.775) ; R238.2@75.055,73.463 R238.2@75.055,73.533
  Top Layer 1 w0.3: R238.2@75.055,73.463 75.946,72.572 v1@75.946,68.707 ; pad.1@76.327,60.373 76.448,60.373 77.543,61.468 v1(77.597,61.468)
  Layer1 w0.3: v1(75.968,68.775) 77.597,67.146 v1(77.597,61.468)
"BSL UART_TX": pad.1@73.827,60.373 R239.2 ZD15.2 | length 17.6
  Top Layer 1 w0.2: ZD15.2@74.833,66.548 74.981,66.548 75.946,66.548 ; R239.2@75.055,75.241 R239.2@75.055,75.311
  Top Layer 1 w0.3: pad.1@73.827,60.373 75.057,61.603 75.057,66.324 ZD15.2@74.833,66.548 ; R239.2@75.055,75.241 76.63,73.666 76.63,67.232 75.946,66.548
BSL_Invoke: pad.1@73.827,63.373 R236.1 ZD16.2 | length 12.6
  Top Layer 1 w0.2: ZD16.2@65.382,67.704 v1(65.382,68.507) 65.382,69.194 R236.1@65.405,69.217
  Top Layer 1 w0.3: v1(73.279,64.77) 73.279,64.716 73.597,64.397 73.597,63.927 73.827,63.698 pad.1@73.827,63.373
  Layer1 w0.3: v1(65.382,68.507) 69.542,68.507 v1(73.279,64.77)
CC1: C115.1 R116.1 USBC2.A5 ZD2.2 | length 92
  Top Layer 1 w0.2: C115.1@89.154,95.379 89.215,95.318 v1(89.215,94.581) ; v1(141.946,77.466) 141.948,77.468 142.903,77.468 142.905,77.47 ZD2.2@142.919,77.456 ; v1(147.238,75.132) v1@147.314,75.132
  Top Layer 1 w0.254: v1@147.314,75.132 147.513,75.331 USBC2.A5@148.513,75.331
  Layer1 w0.3: v1(89.215,94.581) 94.457,99.822 141.986,99.822 144.653,97.155 144.653,76.454 145.975,75.132 v1(147.238,75.132)
  Layer2 w0.3: v1(141.946,77.466) 143.425,77.466 145.759,75.132 v1(147.238,75.132)
CC2: C114.1 R117.2 USBC2.B5 ZD3.2 | length 93.6
  Top Layer 1 w0.2: v1(87.376,94.615) C114.1@87.376,95.379
  Top Layer 1 w0.254: v1(147.206,78.319) 147.216,78.329 148.511,78.329 USBC2.B5@148.513,78.331
  Top Layer 1 w0.3: v1(141.959,82.433) 141.964,82.428 143,82.428 ZD3.2@143.005,82.423
  Layer1 w0.3: v1(87.376,94.615) 94.107,101.346 143.51,101.346 146.304,98.552 146.304,79.221 v1(147.206,78.319)
  Layer2 w0.3: v1(141.959,82.433) 143.22,82.433 147.106,78.547 147.106,78.473 147.206,78.373 v1(147.206,78.319)
COLD_HOT: IC201.14 Q305.1 R324.2 | length 39.2
  Top Layer 1 w0.2: R324.2@77.214,55.88 77.214,54.34 Q305.1@77.406,54.148
  Top Layer 1 w0.254: 60.96,76.331 60.636,76.007 60.636,59.589 61.932,58.293 76.2,58.293 76.917,57.576 76.917,56.284 77.243,55.957 R324.2@77.243,55.887 ; 60.96,76.339 IC201.14@62.497,76.339
D+: IC101.26 USBC2.A6 USBC2.B6 ZD5.2 | length 88.2
  Top Layer 1 w0.2: IC101.26@87.581,90.317 87.581,90.492 88.091,91.002 88.208,91.002 v1(88.265,91.059)
  Top Layer 1 w0.254: v1(147.222,76.829) v1@147.363,76.829 ; USBC2.A6@148.513,76.331 148.511,76.333 147.738,76.333 147.363,76.708 v1@147.363,76.829 ; USBC2.B6@148.513,77.331 148.511,77.329 147.545,77.329 147.396,77.18 147.396,76.863 v1@147.363,76.829
  Top Layer 1 w0.3: v1(141.956,80.745) 141.969,80.758 142.991,80.758 ZD5.2@143.005,80.772
  Layer1 w0.3: v1(88.265,91.059) 92.249,95.043 92.249,95.114 96.195,99.06 140.903,99.06 143.571,96.392 143.571,82.36 v1(141.956,80.745)
  Layer2 w0.3: v1(141.956,80.745) 143.307,80.745 v1(147.222,76.829)
D-: "USBC2.A7 D-" IC101.27 USBC2.B7 ZD6.2 | length 100.4
  Top Layer 1 w0.2: IC101.27@87.181,90.317 87.181,90.794 87.407,91.02 v1(87.407,91.101)
  Top Layer 1 w0.254: v1(147.259,75.88) 147.306,75.833 148.511,75.833 USBC2.B7@148.513,75.831 148.515,75.833 149.288,75.833 149.54,76.085 149.54,76.577 149.288,76.829 148.515,76.829 148.513,76.831
  Top Layer 1 w0.3: v1(141.951,79.083) 141.97,79.102 142.986,79.102 ZD6.2@143.005,79.121
  Layer1 w0.3: v1(87.407,91.101) 87.407,93.63 90.805,97.028 92.606,98.829 94.361,100.584 142.748,100.584 145.542,97.79 145.542,76.835 146.497,75.88 v1(147.259,75.88)
  Layer2 w0.3: v1(141.951,79.083) 142.964,79.083 146.179,75.868 147.248,75.868 v1(147.259,75.88)
GND: C102.2 C103.2 C106.2 C107.2 C108.2 C109.2 C110.2 C111.2 C112.2 C113.2 C114.2 C115.2 C116.2 C117.2 C118.2 C119.2 C120.2 C121.1 C213.2 C214.2 C215.1 C216.1 C301.2 C302.2 C303.2 C304.2 C306.2 C307.1 C308.2 C309.2 C310.2 C311.2 C312.2 C313.2 C314.2 C315.2 C316.2 C317.2 C318.1 C319.2 C320.1 C321.1 C322.1 C323.1 C324.2 C325.2 C326.2 IC101.0@84.216,88.392 IC101.11 IC101.12 IC101.14 IC101.16 IC101.17 IC101.31 IC103.1 IC104.3 IC201.0 IC201.5 IC301.15 IC302.2 IC303.1 J1.1 J1.2 LF101.3 NTC101.1 OUTPUT.1 OUTPUT.2 OUTPUT.3 OUTPUT.4 OUTPUT.5 OUTPUT.6 OUTPUT.7 pad.1@78.827,60.373 pad.1@78.827,63.373 pad.1@140.589,104.521 Q301.2 Q302.2 Q303.2 Q304.2 Q305.2 Q306.2 R108.1 R112.1 R115.1 R119.2 R120.2 R228.2 R302.1 R304.2 R307.2 R309.1 R312.1 R315.1 R318.1 R321.1 R324.1 R328.1 R333.1 U?1.1 U?1.2 U?1.3 U?2.1 U?2.2 U?2.3 U?3.1 U?3.2 U?3.3 U?4.1 U?4.2 U?4.3 U?5.1 U?5.2 U?5.3 U?6.1 U?6.2 U?6.3 U?7.1 U?7.2 U?7.3 U?8.1 U?8.2 U?8.3 U?9.1 U?9.2 U?9.3 U?10.1 U?10.2 U?10.3 U?11.1 U?11.2 U?11.3 U?.1 U?.2 U?.3 ZD4.1 ZD7.1 ZD8.1 ZD9.1 ZD10.1 ZD11.1 ZD12.1 ZD13.1 ZD14.1 ZD15.1 ZD16.1 | length 94.1
  Top Layer 1 w0.2: C120.2@80.419,96.327 C120.2@80.489,96.327 ; IC101.11@84.381,86.467 84.381,88.227 IC101.0@84.216,88.392 84.266,88.392 85.581,89.707 IC101.31@85.581,90.317 C103.2@85.581,91.567 ; IC101.12@84.781,86.467 84.781,87.243 v1(84.862,87.324) ; IC101.0@85.344,87.249 85.581,87.012 IC101.14@85.581,86.467 ; C304.2@85.58,57.783 85.715,57.918 IC301.15@87.377,57.918 ; C103.2@85.743,91.567 C103.2@85.977,91.801 ; IC101.16@86.381,86.467 86.381,86.292 v1@86.75,85.923 ; v1(86.768,85.705) 86.781,85.718 IC101.17@86.781,86.467 ; C110.2@93.218,91.328 C110.2@93.202,91.312 93.202,91.112 C110.2@93.602,90.712 ; C316.2@93.646,65.032 C316.2@93.646,65.102 ; C116.2@97.433,93.271 C116.2@97.596,93.108 C116.2@97.666,93.108 ; C121.1@101.152,85.111 C121.1@101.279,85.238
  Top Layer 1 w0.254: Q301.2@54.103,54.138 54.103,54.298 54.487,54.682 R312.1@54.487,55.88 ; Q302.2@59.69,54.138 59.884,54.332 R315.1@59.884,55.88 ; R228.2@62.357,83.183 62.358,83.184 63.234,83.184 v1(63.235,83.185) ; v1@64.617,80.497 v1(64.569,80.544) 64.569,80.477 64.647,80.4 IC201.5@64.647,79.489 64.647,77.339 IC201.0@64.897,77.089 ; Q303.2@64.962,54.138 65.155,54.332 R318.1@65.155,55.88 ; Q304.2@70.294,54.138 70.552,54.395 R321.1@70.552,55.88 ; Q305.2@75.501,54.138 75.694,54.331 R324.1@75.694,55.88 ; C114.2@87.376,96.899 87.439,96.963 C114.2@87.503,96.963 ; C115.2@88.963,96.963 C115.2@89.027,97.026 ; C117.2@91.185,96.649 C117.2@91.326,96.508 ; C113.2@92.583,84.455 92.583,84.525 93.202,85.144 C112.2@93.202,86.486 C110.2@93.202,91.112 ; C102.2@93.373,96.525 C102.2@93.514,96.667
  Bottom Layer 1 w0.2: J1.2@146.06,104.567 J1.2@146.136,104.643
  Bottom Layer 1 w0.3: 99.003,92.964 108.839,92.964 111.633,95.758 147.193,95.758 152.527,90.424 v1(152.527,87.249)
  other v1: 52.498,48.084 140.135,48.246 148.463,48.26 115.951,48.387 145.586,48.64 81.724,49.23 80.427,49.258 83.846,49.244 117.859,49.946 94.911,53.831 92.134,54.21 93.454,54.21 118.083,55.231 53.373,55.284 128.778,55.499 82.148,55.564 81.347,55.6 69.702,55.874 58.82,55.897 74.574,55.978 64.008,56.007 144.145,56.134 53.467,56.261 82.042,57.912 94.615,58.42 82.042,58.674 94.724,59.29 57.193,59.733 53.721,60.706 143.493,60.694 152.654,61.341 94.688,61.961 101.476,62.572 94.625,62.699 56.734,63.246 94.636,64.503 71.12,65.532 88.374,65.659 53.721,66.167 88.362,66.396 63.243,66.813 63.912,66.853 72.263,67.419 55.416,68.733 72.274,69.119 116.535,70.202 78.627,71.687 112.041,74.966 82.869,75.102 66.201,75.622 63.619,75.667 64.431,75.667 65.335,75.662 117.726,76.103 63.636,76.287 64.404,76.304 66.186,76.314 65.248,76.322 63.627,76.951 64.431,76.968 65.272,76.965 66.201,77.053 63.645,77.658 66.081,77.658 64.439,77.702 65.243,77.702 109.979,77.935 63.627,78.359 64.396,78.348 65.182,78.383 66.072,78.374 70.756,80.616 118.872,81.788 58.039,83.566 102.362,83.947 86.317,84.171 71.249,84.22 71.96,84.329 102.362,85.09 57.785,85.725 66.294,86.106 61.169,86.516 66.304,86.894 84.038,87.359 110.871,87.376 53.467,87.884 84.845,87.896 84.048,87.958 83.371,87.988 83.27,88.608 84,88.617 84.836,88.646 104.148,88.736 84.695,89.286 83.991,89.321 83.251,89.362 59.619,89.945 115.344,90.611 106.594,91.238 102.616,91.313 110.744,91.313 79.248,92.837 98.552,92.837 60.198,93.218 79.248,93.599 70.448,93.985 54.582,94.217 90.678,94.615 91.145,95.459 88.248,96.471 65.744,97.019 88.233,97.299 68.278,99.465 57.023,100.33 76.708,101.219 83.226,102.215 76.835,102.489 61.254,102.935 67.564,102.997 76.835,103.759 52.578,105.029
I2Ct-SCL: C323.2 IC101.9 IC201.2 IC301.13 R102.1 R329.1 ZD7.2 | length 75.1
  Top Layer 1 w0.2: IC101.9@83.581,86.467 83.581,85.771 83.708,85.644 83.708,85.53 83.725,85.513 83.725,84.866 R102.1@83.693,84.834 ; IC301.13@87.934,58.743 87.934,59.664 88.066,59.796 v1(88.066,59.877) ; ZD7.2@104.09,56.531 ZD7.2@104.134,56.487
  Top Layer 1 w0.254: IC201.2@66.147,79.489 66.149,79.491 66.149,79.974 66.478,80.303 v1(66.478,80.369)
  Layer1 w0.3: v1(83.725,85.546) 83.725,68.961 84.868,67.818 88.375,67.818 89.408,66.785 89.408,61.219 ; v1(88.066,59.877) 89.408,61.219 ; v1(103.135,60.781) 102.36,61.556 96.025,61.556 95.688,61.219 89.408,61.219
  Layer2 w0.3: v1(66.478,80.369) 66.478,82.48 66.935,82.937 81.103,82.937 83.712,85.546 v1(83.725,85.546) ; v1(103.135,60.781) 104.188,59.728 v1(104.188,55.58)
I2Ct-SDA: C324.1 IC101.8 IC201.1 IC301.12 R101.1 R330.1 ZD8.2 | length 75.5
  Top Layer 1 w0.2: v1@67.229,79.819 v1(67.31,79.819) ; R101.1@81.915,84.836 81.985,84.836 83.181,86.032 IC101.8@83.181,86.467 ; IC301.12@88.334,58.743 88.334,59.283 88.995,59.944 v1(89.058,59.944)
  Top Layer 1 w0.254: IC201.1@66.647,79.489 66.647,79.66 66.649,79.662 66.82,79.662 66.93,79.772 67.263,79.772 v1(67.31,79.819)
  Layer1 w0.3: v1(67.31,79.819) 75.505,79.819 80.474,84.789 v1(80.474,84.843) ; v1@80.512,84.773 80.512,84.458 80.528,84.443 80.528,62.982 84.816,58.694 87.808,58.694 88.72,59.606 88.72,59.608 88.987,59.875 88.987,59.929 89.002,59.944 104.757,59.944 v1(105.878,61.065)
  Layer2 w0.3: v1(105.878,55.477) v1(105.878,61.065)
INT_BATT_IC: C325.1 R230.2 R233.2 R331.1 ZD9.2 | length 84.9
  Top Layer 1 w0.2: R233.2@54.485,78.359 v1(54.485,79.248) R230.2@54.485,80.137 ; ZD9.2@102.381,56.489 ZD9.2@102.4,56.508
  Layer2 w0.3: v1(101.575,60.902) 102.347,60.131 v1(102.347,57.465)
  Layer2 w0.5: v1(54.485,79.248) 54.485,57.529 61.849,50.165 101.346,50.165 102.347,51.166 v1(102.347,57.465)
INT_BQ25622: IC301.11 R235.2 R237.1 | length 69.3
  Top Layer 1 w0.2: v1(62.572,69.334) 63.49,69.334 R235.2@63.5,69.344 ; IC301.11@88.734,58.743 88.734,58.943 89.134,59.343 89.663,59.343 v1(89.716,59.29)
  Layer1 w0.3: v1(53.535,81.915) 53.535,72.83 57.031,69.334 v1(62.572,69.334)
  Layer2 w0.3: v1(62.572,69.334) 62.103,68.865 62.103,55.88 64.427,53.556 88.787,53.556 89.702,54.472 89.702,59.276 v1(89.716,59.29)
